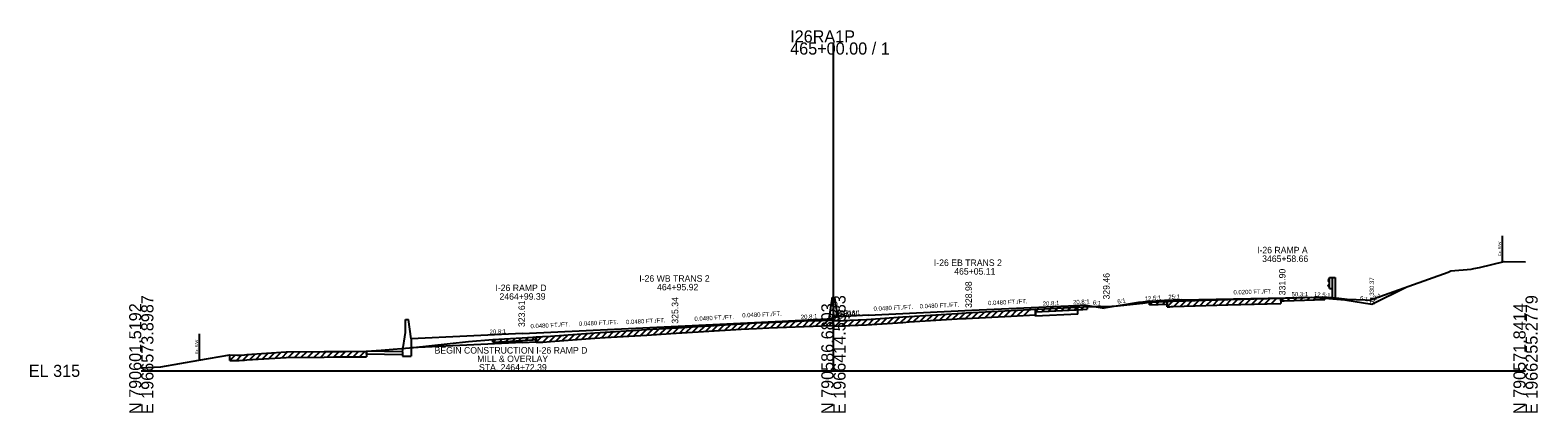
# Model space of a CAD drawing. Extents: x -44 to 4323, y -10 to 9601.
# Drawn here: x 3974.3 to 4322.8, y 3490.3 to 3578.7 of the extents above; entities that cross this region are included whole.
import ezdxf

# ---------------------------------------------------------------- set-up
doc = ezdxf.new("R2010")
doc.units = 0
for name, color, linetype in [('1', 7, 'Continuous'), ('DateStamp', 7, 'Continuous'), ('NotForConst', 7, 'Continuous'), ('QCQA', 7, 'Continuous'), ('RD_SHT_Bndy', 7, 'Continuous'), ('RD_SHT_Iplotshp', 7, 'Continuous'), ('RD_SHT_TX', 7, 'Continuous'), ('RD_XS_Base', 7, 'Continuous'), ('RD_XS_EarthShd', 7, 'Continuous'), ('RD_XS_ExGround', 7, 'Continuous'), ('RD_XS_ExPaveRet', 7, 'Continuous'), ('RD_XS_MatchLine', 7, 'Continuous'), ('RD_XS_MedBWall', 7, 'Continuous'), ('RD_XS_Misc_Line', 7, 'Continuous'), ('RD_XS_Pave', 7, 'Continuous'), ('RD_XS_PaveOvlay', 7, 'Continuous'), ('RD_XS_PaveShd', 7, 'Continuous'), ('RD_XS_TX_Elev_PR', 7, 'Continuous'), ('RD_XS_TX_Profile', 7, 'Continuous'), ('RD_XS_TX_ShdSlope', 7, 'Continuous'), ('RD_XS_TX_Slope', 7, 'Continuous'), ('seal', 7, 'Continuous'), ('TR SN EXTRUDED PANEL SIGNS - GROUND MOUNTED', 7, 'Continuous')]:
    doc.layers.add(name, color=color, linetype=linetype)

msp = doc.modelspace()

# ---------------------------------------------------------------- linework, layer by layer
at = {"layer": 'DateStamp'}
msp.add_lwpolyline([(4000, 3500.7), (4004.5, 3500.93), (4013.27, 3502.5), (4020.48, 3503.67), (4022.23, 3503.64), (4022.59, 3503.64), (4023.87, 3503.72), (4024.38, 3503.76), (4033.5, 3504.36), (4042.31, 3504.44), (4044.82, 3504.48), (4047.22, 3504.48), (4052.09, 3504.51), (4055.48, 3504.78), (4062.96, 3505.42), (4075.65, 3506.79), (4081.3, 3507.24), (4088.03, 3507.65), (4090.53, 3507.8), (4092.44, 3507.89), (4092.79, 3507.9), (4094.62, 3508.04), (4104.87, 3508.81), (4107.24, 3508.95), (4116.85, 3509.52), (4122.4, 3509.87), (4129.98, 3510.33), (4138.71, 3510.86), (4142.24, 3511.07), (4145.03, 3511.18), (4153.26, 3511.53), (4157.43, 3511.66), (4158.7, 3511.7), (4160, 3511.65), (4160.42, 3511.64), (4161.49, 3511.59), (4163.82, 3511.71), (4167.63, 3511.88), (4176.05, 3512.45), (4177.51, 3512.55), (4188.58, 3513.24), (4189.71, 3513.31), (4190.72, 3513.37), (4201.05, 3513.92), (4217.63, 3514.81), (4218.69, 3514.86), (4219.15, 3514.85), (4219.7, 3514.86), (4223.07, 3514.88), (4225.67, 3515.04), (4231.5, 3515.63), (4233.09, 3515.86), (4237.31, 3516.03), (4237.76, 3516.06), (4238.17, 3516.08), (4238.52, 3516.08), (4251.18, 3516.48), (4260.29, 3516.71), (4263.76, 3516.81), (4264.22, 3516.82), (4273.58, 3517.08), (4274.13, 3517.02), (4276.87, 3516.76), (4278.73, 3516.54), (4282.94, 3516.38), (4283.89, 3516.29), (4302.08, 3522.81), (4302.73, 3523.07), (4307.44, 3523.49), (4308.05, 3523.62), (4309.38, 3523.91), (4315.07, 3525.28), (4320, 3525.19)], dxfattribs=at)
at = {"layer": 'NotForConst'}
for p, q in [((4259.71, 3515.45), (4260.99, 3516.73)), ((4261.21, 3515.49), (4262.5, 3516.77)), ((4263.45, 3516.17), (4264.1, 3516.82)), ((4264.95, 3516.22), (4265.6, 3516.86)), ((4266.46, 3516.26), (4267.1, 3516.9)), ((4267.96, 3516.3), (4268.6, 3516.94)), ((4269.46, 3516.34), (4270.11, 3516.98)), ((4270.97, 3516.38), (4271.61, 3517.02)), ((4272.47, 3516.42), (4273.12, 3517.07)), ((4187.55, 3511.93), (4188.88, 3513.26)), ((4189.05, 3512.02), (4190.38, 3513.35)), ((4190.55, 3512.11), (4191.88, 3513.43)), ((4192.06, 3512.19), (4193.38, 3513.51)), ((4193.56, 3512.27), (4194.89, 3513.59)), ((4195.06, 3512.35), (4196.39, 3513.67)), ((4196.57, 3512.43), (4197.89, 3513.75)), ((4198.07, 3512.51), (4199.4, 3513.83)), ((4199.58, 3512.59), (4200.9, 3513.91)), ((4201.08, 3512.67), (4202.4, 3513.99)), ((4202.58, 3512.75), (4203.91, 3514.07)), ((4204.09, 3512.83), (4205.41, 3514.16)), ((4206.69, 3513.6), (4207.35, 3514.26)), ((4208.19, 3513.68), (4208.85, 3514.34)), ((4209.69, 3513.76), (4210.35, 3514.42)), ((4211.2, 3513.84), (4211.86, 3514.5)), ((4212.7, 3513.92), (4213.36, 3514.58)), ((4214.2, 3514), (4214.87, 3514.66)), ((4215.71, 3514.08), (4216.37, 3514.74)), ((4217.21, 3514.16), (4217.87, 3514.82)), ((4233.09, 3515.23), (4233.74, 3515.88)), ((4234.59, 3515.29), (4235.24, 3515.95)), ((4236.09, 3515.36), (4236.75, 3516.01)), ((4237.15, 3514.78), (4238.46, 3516.08)), ((4238.66, 3514.84), (4239.95, 3516.13)), ((4240.16, 3514.88), (4241.45, 3516.17)), ((4241.66, 3514.93), (4242.96, 3516.22)), ((4243.17, 3514.98), (4244.46, 3516.27)), ((4244.67, 3515.02), (4245.96, 3516.31)), ((4246.17, 3515.07), (4247.47, 3516.36)), ((4247.68, 3515.12), (4248.97, 3516.41)), ((4249.18, 3515.16), (4250.47, 3516.45)), ((4250.69, 3515.21), (4251.97, 3516.5)), ((4252.19, 3515.25), (4253.48, 3516.54)), ((4253.69, 3515.29), (4254.98, 3516.58)), ((4255.2, 3515.33), (4256.48, 3516.61)), ((4256.7, 3515.37), (4257.99, 3516.65)), ((4258.2, 3515.41), (4259.49, 3516.69)), ((4119.89, 3508.46), (4121.22, 3509.79)), ((4121.39, 3508.55), (4122.73, 3509.89)), ((4122.89, 3508.65), (4124.23, 3509.98)), ((4124.4, 3508.74), (4125.73, 3510.07)), ((4125.9, 3508.83), (4127.24, 3510.16)), ((4127.4, 3508.92), (4128.74, 3510.25)), ((4128.91, 3509.01), (4130.24, 3510.34)), ((4130.41, 3509.1), (4131.75, 3510.43)), ((4131.92, 3509.19), (4133.25, 3510.53)), ((4133.42, 3509.29), (4134.75, 3510.62)), ((4134.92, 3509.38), (4136.26, 3510.71)), ((4136.43, 3509.47), (4137.76, 3510.8)), ((4137.93, 3509.56), (4139.26, 3510.89)), ((4139.43, 3509.65), (4140.77, 3510.98)), ((4140.94, 3509.74), (4142.27, 3511.08)), ((4142.44, 3509.83), (4143.74, 3511.13)), ((4143.94, 3509.89), (4145.25, 3511.19)), ((4145.45, 3509.95), (4146.76, 3511.26)), ((4146.95, 3510.02), (4148.26, 3511.32)), ((4148.45, 3510.08), (4149.76, 3511.38)), ((4149.96, 3510.14), (4151.27, 3511.45)), ((4151.46, 3510.21), (4152.77, 3511.51)), ((4152.97, 3510.27), (4154.26, 3511.56)), ((4154.47, 3510.32), (4155.76, 3511.61)), ((4155.97, 3510.37), (4157.27, 3511.66)), ((4157.48, 3510.41), (4158.76, 3511.69)), ((4158.98, 3510.44), (4160.19, 3511.65)), ((4160.48, 3510.39), (4161.7, 3511.6)), ((4161.99, 3510.37), (4163.3, 3511.68)), ((4163.49, 3510.44), (4164.81, 3511.75)), ((4164.99, 3510.51), (4166.31, 3511.82)), ((4166.5, 3510.58), (4167.82, 3511.9)), ((4168, 3510.66), (4169.35, 3512)), ((4169.5, 3510.76), (4170.85, 3512.1)), ((4171.01, 3510.86), (4172.35, 3512.2)), ((4172.51, 3510.96), (4173.86, 3512.31)), ((4174.02, 3511.07), (4175.36, 3512.41)), ((4175.52, 3511.17), (4176.86, 3512.51)), ((4177.02, 3511.27), (4178.36, 3512.61)), ((4178.53, 3511.37), (4179.86, 3512.7)), ((4180.03, 3511.46), (4181.37, 3512.79)), ((4181.53, 3511.55), (4182.87, 3512.89)), ((4183.04, 3511.65), (4184.37, 3512.98)), ((4184.54, 3511.74), (4185.88, 3513.08)), ((4186.04, 3511.84), (4187.38, 3513.17)), ((4081.3, 3506.62), (4081.96, 3507.28)), ((4082.8, 3506.71), (4083.47, 3507.37)), ((4084.3, 3506.8), (4084.97, 3507.47)), ((4085.81, 3506.89), (4086.47, 3507.56)), ((4087.31, 3506.98), (4087.98, 3507.65)), ((4088.81, 3507.07), (4089.48, 3507.74)), ((4090.32, 3507.16), (4090.98, 3507.82)), ((4091.32, 3506.59), (4092.63, 3507.9)), ((4092.82, 3506.65), (4094.18, 3508)), ((4094.33, 3506.77), (4095.68, 3508.12)), ((4095.83, 3506.88), (4097.19, 3508.23)), ((4097.33, 3506.99), (4098.69, 3508.34)), ((4098.84, 3507.1), (4100.19, 3508.46)), ((4100.34, 3507.22), (4101.7, 3508.57)), ((4101.84, 3507.33), (4103.2, 3508.68)), ((4103.35, 3507.44), (4104.7, 3508.79)), ((4104.85, 3507.56), (4106.19, 3508.89)), ((4106.36, 3507.65), (4107.69, 3508.98)), ((4107.86, 3507.74), (4109.19, 3509.07)), ((4109.36, 3507.83), (4110.69, 3509.15)), ((4110.87, 3507.91), (4112.2, 3509.24)), ((4112.37, 3508), (4113.7, 3509.33)), ((4113.87, 3508.09), (4115.2, 3509.42)), ((4115.38, 3508.18), (4116.71, 3509.51)), ((4116.88, 3508.27), (4118.22, 3509.6)), ((4118.38, 3508.36), (4119.72, 3509.7)), ((4020.48, 3502.42), (4021.71, 3503.65)), ((4021.98, 3502.4), (4023.27, 3503.68)), ((4023.48, 3502.45), (4024.82, 3503.79)), ((4024.98, 3502.55), (4026.32, 3503.88)), ((4026.48, 3502.65), (4027.82, 3503.98)), ((4027.98, 3502.75), (4029.32, 3504.08)), ((4029.48, 3502.84), (4030.82, 3504.18)), ((4030.98, 3502.94), (4032.32, 3504.28)), ((4032.48, 3503.04), (4033.8, 3504.36)), ((4033.98, 3503.12), (4035.24, 3504.38)), ((4035.48, 3503.13), (4036.74, 3504.39)), ((4036.98, 3503.14), (4038.24, 3504.41)), ((4038.48, 3503.16), (4039.74, 3504.42)), ((4039.98, 3503.17), (4041.24, 3504.43)), ((4041.48, 3503.19), (4042.75, 3504.45)), ((4042.98, 3503.2), (4044.25, 3504.47)), ((4044.48, 3503.23), (4045.74, 3504.48)), ((4045.98, 3503.23), (4047.23, 3504.48)), ((4047.48, 3503.24), (4048.74, 3504.49)), ((4048.98, 3503.25), (4050.24, 3504.5)), ((4050.48, 3503.25), (4051.74, 3504.51))]:
    msp.add_line(p, q, dxfattribs=at)
at = {"layer": 'QCQA'}
for p, q in [((4177.51, 3512.55), (4188.58, 3513.24)), ((4188.58, 3513.24), (4189.71, 3513.31)), ((4189.71, 3513.31), (4190.72, 3513.37)), ((4190.72, 3513.37), (4201.05, 3513.92)), ((4201.05, 3513.92), (4206.69, 3514.22)), ((4116.85, 3509.52), (4122.4, 3509.87)), ((4122.4, 3509.87), (4129.98, 3510.33)), ((4129.98, 3510.33), (4138.71, 3510.86)), ((4138.71, 3510.86), (4142.24, 3511.07)), ((4142.24, 3511.07), (4145.03, 3511.18)), ((4145.03, 3511.18), (4153.26, 3511.53)), ((4153.26, 3511.53), (4157.43, 3511.66)), ((4157.43, 3511.66), (4158.7, 3511.7)), ((4158.7, 3511.7), (4160, 3511.65)), ((4160, 3511.65), (4160.42, 3511.64)), ((4160.42, 3511.64), (4161.49, 3511.59)), ((4161.49, 3511.59), (4163.82, 3511.71)), ((4163.82, 3511.71), (4167.63, 3511.88)), ((4167.63, 3511.88), (4176.05, 3512.45)), ((4176.05, 3512.45), (4177.51, 3512.55)), ((4091.32, 3507.84), (4092.44, 3507.89)), ((4091.32, 3507.84), (4091.32, 3506.73)), ((4092.44, 3507.89), (4092.79, 3507.9)), ((4092.79, 3507.9), (4094.62, 3508.04)), ((4094.62, 3508.04), (4104.87, 3508.81)), ((4104.87, 3508.81), (4107.24, 3508.95)), ((4107.24, 3508.95), (4116.85, 3509.52))]:
    msp.add_line(p, q, dxfattribs=at)
at = {"layer": 'RD_SHT_Bndy'}
for p, q in [((4160, 3500), (4160, 3575.85)), ((4000, 3500), (4160, 3500)), ((4160, 3500), (4320, 3500))]:
    msp.add_line(p, q, dxfattribs=at)
at = {"layer": 'RD_SHT_Iplotshp'}
for p, q in [((4263.45, 3516.8), (4263.45, 3515.55)), ((4263.45, 3516.17), (4263.45, 3516.8)), ((4273.58, 3517.08), (4273.58, 3516.45)), ((4206.69, 3514.22), (4206.69, 3512.97)), ((4206.69, 3513.6), (4206.69, 3514.22)), ((4206.69, 3513.6), (4217.63, 3514.19)), ((4217.63, 3514.19), (4218.69, 3514.24)), ((4218.69, 3514.86), (4218.69, 3514.24)), ((4233.09, 3515.23), (4233.09, 3515.86)), ((4233.09, 3515.23), (4237.15, 3515.4)), ((4237.15, 3514.78), (4237.15, 3516.03)), ((4237.15, 3516.03), (4237.15, 3515.4)), ((4237.15, 3514.78), (4237.31, 3514.78)), ((4237.31, 3514.78), (4237.76, 3514.81)), ((4237.76, 3514.81), (4238.17, 3514.83)), ((4238.17, 3514.83), (4238.52, 3514.83)), ((4238.52, 3514.83), (4251.18, 3515.23)), ((4251.18, 3515.23), (4260.29, 3515.46)), ((4260.29, 3515.46), (4263.45, 3515.55)), ((4263.45, 3516.17), (4263.76, 3516.18)), ((4263.76, 3516.18), (4264.22, 3516.2)), ((4264.22, 3516.2), (4273.58, 3516.45)), ((4138.71, 3509.61), (4142.24, 3509.82)), ((4142.24, 3509.82), (4145.03, 3509.93)), ((4145.03, 3509.93), (4153.26, 3510.28)), ((4153.26, 3510.28), (4157.43, 3510.41)), ((4157.43, 3510.41), (4158.7, 3510.45)), ((4158.7, 3510.45), (4160, 3510.4)), ((4160, 3510.4), (4160.42, 3510.39)), ((4160.42, 3510.39), (4161.49, 3510.34)), ((4161.49, 3510.34), (4163.82, 3510.46)), ((4163.82, 3510.46), (4167.63, 3510.63)), ((4167.63, 3510.63), (4176.05, 3511.2)), ((4176.05, 3511.2), (4177.51, 3511.3)), ((4177.51, 3511.3), (4188.58, 3511.99)), ((4188.58, 3511.99), (4189.71, 3512.06)), ((4189.71, 3512.06), (4190.72, 3512.12)), ((4190.72, 3512.12), (4201.05, 3512.67)), ((4201.05, 3512.67), (4206.69, 3512.97)), ((4081.3, 3506.62), (4081.3, 3507.24)), ((4081.3, 3506.62), (4088.03, 3507.02)), ((4088.03, 3507.02), (4090.53, 3507.18)), ((4090.53, 3507.18), (4091.32, 3507.21)), ((4091.32, 3506.59), (4091.32, 3507.84)), ((4091.32, 3507.84), (4091.32, 3507.21)), ((4091.32, 3506.59), (4092.44, 3506.64)), ((4092.44, 3506.64), (4092.79, 3506.65)), ((4092.79, 3506.65), (4094.62, 3506.79)), ((4094.62, 3506.79), (4104.87, 3507.56)), ((4104.87, 3507.56), (4107.24, 3507.7)), ((4107.24, 3507.7), (4116.85, 3508.27)), ((4116.85, 3508.27), (4122.4, 3508.62)), ((4122.4, 3508.62), (4129.98, 3509.08)), ((4129.98, 3509.08), (4138.71, 3509.61)), ((4020.48, 3502.42), (4020.48, 3503.67)), ((4024.38, 3502.51), (4033.5, 3503.11)), ((4033.5, 3503.11), (4042.31, 3503.19)), ((4042.31, 3503.19), (4044.82, 3503.23)), ((4044.82, 3503.23), (4047.22, 3503.23)), ((4047.22, 3503.23), (4052.09, 3503.26)), ((4052.09, 3504.51), (4052.09, 3503.26)), ((4020.48, 3502.42), (4022.23, 3502.39)), ((4022.23, 3502.39), (4022.59, 3502.39)), ((4022.59, 3502.39), (4023.87, 3502.47)), ((4023.87, 3502.47), (4024.38, 3502.51))]:
    msp.add_line(p, q, dxfattribs=at)
at = {"layer": 'RD_XS_Base'}
for p, q in [((4274.65, 3521.42), (4274.38, 3520.98)), ((4274.38, 3520.98), (4274.38, 3520.87)), ((4274.38, 3520.87), (4274.65, 3520.43)), ((4274.65, 3521.58), (4275.32, 3521.58)), ((4274.65, 3519.01), (4274.65, 3521.58)), ((4275.32, 3521.58), (4275.98, 3521.58)), ((4275.32, 3521.58), (4275.32, 3516.63)), ((4275.98, 3521.58), (4275.98, 3516.52)), ((4274.38, 3519.72), (4274.65, 3520.16)), ((4274.38, 3519.61), (4274.38, 3519.72)), ((4274.65, 3519.17), (4274.38, 3519.61)), ((4274.65, 3519.01), (4275.32, 3519.01))]:
    msp.add_line(p, q, dxfattribs=at)
at = {"layer": 'RD_XS_ExPaveRet'}
msp.add_line((4060.42, 3504.4), (4060.42, 3503.4), dxfattribs=at)
at = {"layer": 'RD_XS_Misc_Line'}
for p, q in [((4270.5, 3516.99), (4270.5, 3517.02)), ((4206.69, 3512.64), (4206.69, 3514.22)), ((4216, 3514.57), (4216, 3515.13)), ((4216, 3514.57), (4216.5, 3514.59)), ((4216.5, 3513.11), (4216.5, 3514.59)), ((4236.5, 3516), (4236.5, 3516.27)), ((4216.5, 3513.11), (4206.69, 3512.64)), ((4088.13, 3506.57), (4062.42, 3505.34)), ((4088.13, 3506.57), (4091.32, 3506.73)), ((4052.09, 3503.85), (4052.09, 3504.51)), ((4060.42, 3503.73), (4052.09, 3503.85))]:
    msp.add_line(p, q, dxfattribs=at)
at = {"layer": 'RD_XS_Pave'}
for p, q in [((4274.5, 3516.7), (4278.25, 3516.4)), ((4284.45, 3515.37), (4292.39, 3519.34)), ((4218, 3515.23), (4222.57, 3514.46)), ((4230.5, 3515.79), (4222.57, 3514.46)), ((4278.25, 3516.4), (4284.45, 3515.37))]:
    msp.add_line(p, q, dxfattribs=at)
at = {"layer": 'RD_XS_PaveOvlay'}
for p, q in [((4314.6, 3531.17), (4314.6, 3525.17)), ((4013.37, 3508.52), (4013.37, 3502.52))]:
    msp.add_line(p, q, dxfattribs=at)
at = {"layer": 'RD_XS_PaveShd'}
for p, q in [((4270.5, 3517.02), (4274.5, 3516.7)), ((4216, 3515.13), (4218, 3515.23)), ((4236.5, 3516.27), (4230.5, 3515.79))]:
    msp.add_line(p, q, dxfattribs=at)
at = {"layer": 'RD_XS_TX_Elev_PR'}
for p, q in [((4264.5, 3516.9), (4270.5, 3517.02)), ((4204, 3514.55), (4216, 3515.13)), ((4240.5, 3516.43), (4236.5, 3516.27)), ((4148.13, 3511.5), (4160, 3512.07)), ((4168, 3512.83), (4160, 3512.44)), ((4160, 3512.44), (4160, 3512.07)), ((4088.13, 3508.61), (4062.42, 3507.38)), ((4062.42, 3507.38), (4062.42, 3505.34)), ((4060.42, 3504.4), (4052.09, 3504.51)), ((4060.42, 3504.4), (4060.42, 3503.73))]:
    msp.add_line(p, q, dxfattribs=at)
at = {"layer": 'RD_XS_TX_ShdSlope'}
for p, q in [((4159.67, 3516.94), (4160.33, 3516.94)), ((4159.67, 3516.57), (4159.67, 3516.94)), ((4161, 3512.49), (4160.33, 3516.94)), ((4159, 3512.02), (4159.67, 3516.57)), ((4061.09, 3511.83), (4061.75, 3511.83)), ((4061.09, 3508.85), (4061.09, 3511.83)), ((4062.42, 3507.38), (4061.75, 3511.83)), ((4060.42, 3504.4), (4061.09, 3508.85)), ((4062.42, 3507.38), (4062.42, 3503.4)), ((4060.42, 3503.4), (4062.42, 3503.4))]:
    msp.add_line(p, q, dxfattribs=at)
at = {"layer": 'RD_XS_TX_Slope'}
for p, q in [((4240.5, 3516.43), (4264.5, 3516.9)), ((4168, 3512.83), (4192, 3513.98)), ((4192, 3513.98), (4204, 3514.55)), ((4088.13, 3508.61), (4124.13, 3510.34)), ((4124.13, 3510.34), (4148.13, 3511.5))]:
    msp.add_line(p, q, dxfattribs=at)

# ---------------------------------------------------------------- texts
at = {"layer": '1'}
for s, p in [('I-26 RAMP A', (4257.93, 3527.15)), ('I-26 EB TRANS 2', (4183.22, 3524.23)), ('465+05.11', (4187.92, 3522.23)), ('3465+58.66', (4259.11, 3525.15)), ('I-26 WB TRANS 2', (4115.12, 3520.59)), ('I-26 RAMP D', (4081.86, 3518.43)), ('2464+99.39', (4082.8, 3516.43)), ('464+95.92', (4119.23, 3518.59))]:
    msp.add_text(s, height=1.5, dxfattribs=at).set_placement(p)
at = {"layer": 'RD_SHT_Bndy'}
for s, p in [('465+00.00 / 1', (4150, 3573.05)), ('I26RA1P', (4150, 3575.85)), ('EL 315', (3974, 3498.6))]:
    msp.add_text(s, height=2.8, dxfattribs=at).set_placement(p)
for s, p in [('E 1966573.8987', (4002.8, 3490)), ('E 1966414.5883', (4162.8, 3490)), ('E 1966255.2779', (4322.8, 3490)), ('N 790601.5192', (4000, 3490)), ('N 790586.6803', (4160, 3490)), ('N 790571.8414', (4320, 3490))]:
    msp.add_text(s, height=2.8, rotation=90, dxfattribs=at).set_placement(p)
at = {"layer": 'RD_SHT_TX'}
msp.add_text('326.65', height=1, rotation=90, dxfattribs=at).set_placement((4161, 3511.65))
at = {"layer": 'RD_XS_EarthShd'}
msp.add_text('329.46', height=1.5, rotation=90, dxfattribs=at).set_placement((4223.84, 3516.47))
at = {"layer": 'RD_XS_ExGround'}
for rotation, p in [(2.7481, (4162.41, 3512.81)), (2.7481, (4208.41, 3515.02)), (2.7489, (4152.48, 3511.95)), (2.7489, (4080.54, 3508.5))]:
    msp.add_text('20.8:1', height=1, rotation=rotation, dxfattribs=at).set_placement(p)
at = {"layer": 'RD_XS_MatchLine'}
for s, p in [('BEGIN CONSTRUCTION I-26 RAMP D', (4067.8, 3503.99)), ('MILL & OVERLAY', (4077.66, 3502.02)), ('STA. 2464+72.39', (4078.06, 3500.06))]:
    msp.add_text(s, height=1.5, dxfattribs=at).set_placement(p)
at = {"layer": 'RD_XS_MedBWall'}
for s, rotation, p in [('12.5:1', 4.5734, (4232, 3516.16)), ('12.5:1', 355.4265, (4271.05, 3517.23)), ('20.8:1', 2.7481, (4215.41, 3515.35))]:
    msp.add_text(s, height=1, rotation=rotation, dxfattribs=at).set_placement(p)
at = {"layer": 'RD_XS_PaveOvlay'}
for p in [(4314.35, 3526.55), (4013.12, 3503.9)]:
    msp.add_text('Ex. R/W ', height=0.65, rotation=90, dxfattribs=at).set_placement(p)
at = {"layer": 'RD_XS_TX_Profile'}
for s, p in [('R', (4283.87, 3515.37)), ('WBW', (4159, 3512.02)), ('EBW', (4161, 3512.49))]:
    msp.add_text(s, height=1.5, dxfattribs=at).set_placement(p)
at = {"layer": 'seal'}
for s, p in [(' 328.98', (4192, 3513.98)), (' 331.90', (4264.5, 3516.9)), (' 325.34', (4124.13, 3510.34)), ('323.61', (4088.69, 3510.12))]:
    msp.add_text(s, height=1.5, rotation=90, dxfattribs=at).set_placement(p)
at = {"layer": 'TR SN EXTRUDED PANEL SIGNS - GROUND MOUNTED'}
for s, rotation, p in [('330.37', 90, (4284.95, 3517.37)), ('6:1', 9.4614, (4225.72, 3515.5)), ('25:1', 2.2904, (4237.44, 3516.55)), ('0.0200 FT./FT.', 1.1395, (4252.48, 3517.66)), ('50.3:1', 1.1395, (4265.92, 3517.18)), ('6:1', 350.5386, (4281.64, 3516.35)), ('2:1', 26.5627, (4285.1, 3516.25)), ('0.0480 FT./FT.', 2.75, (4138.94, 3512.32)), ('0.0480 FT./FT.', 2.7481, (4169.3, 3513.85)), ('0.0480 FT./FT.', 2.7481, (4179.95, 3514.4)), ('0.0480 FT./FT.', 2.7481, (4195.77, 3515.16)), ('6:1', 350.5377, (4219.87, 3515.38)), ('0.0480 FT./FT.', 2.75, (4089.99, 3509.82)), ('0.0480 FT./FT.', 2.75, (4101.19, 3510.37)), ('0.0480 FT./FT.', 2.7489, (4112.08, 3510.77)), ('0.0480 FT./FT.', 2.7489, (4127.89, 3511.52))]:
    msp.add_text(s, height=1, rotation=rotation, dxfattribs=at).set_placement(p)

doc.saveas('drawing.dxf')
